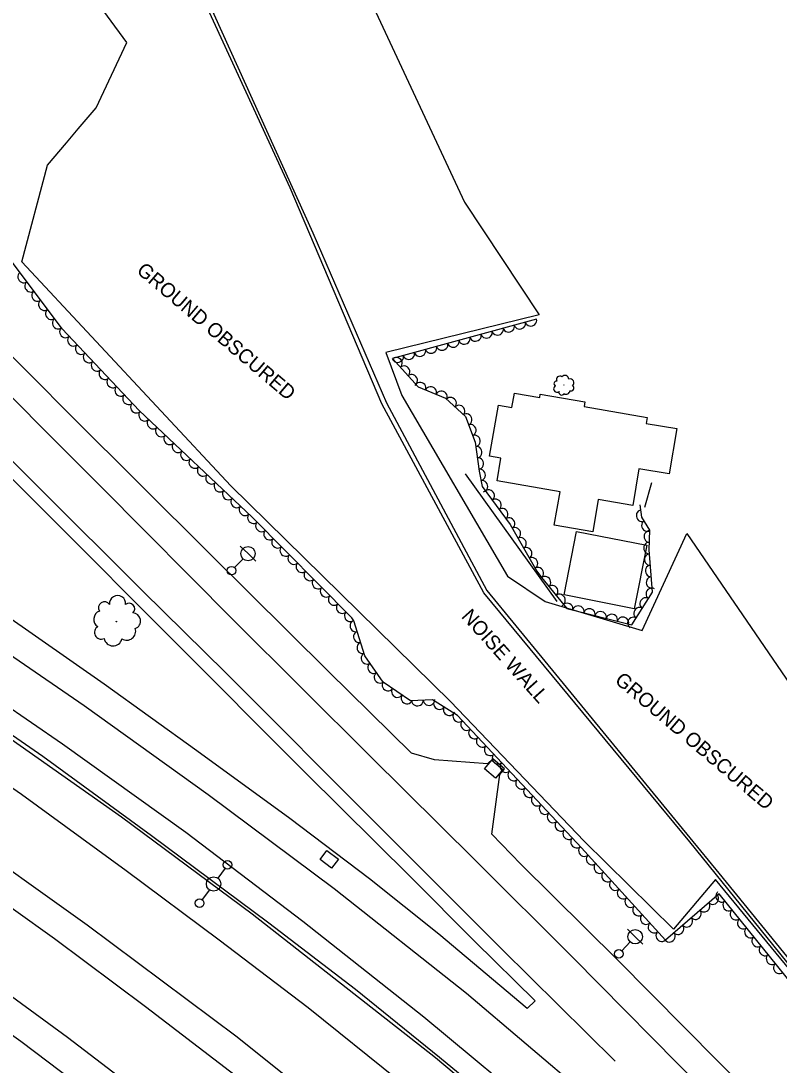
# Model space of a CAD drawing. Extents: x 1722896 to 1754269, y 648279 to 666297.
# Drawn here: x 1730871.3 to 1731135, y 652189.9 to 652553.4 of the extents above; entities that cross this region are included whole.
import ezdxf

# ---------------------------------------------------------------- set-up
doc = ezdxf.new("R2010")
doc.units = 0
for name, color, linetype in [('DESIGN - CENTERLINE - Proposed Text', 7, 'Continuous'), ('DESIGN - SCRATCH - User 1', 7, 'Continuous'), ('SURVEY - CENTERLINE - Preliminary', 7, 'Continuous'), ('SURVEY - CENTERLINE - Preliminary Text', 7, 'Continuous'), ('SURVEY - DRAINAGE - Natural Features', 7, 'Continuous'), ('SURVEY - DTM - Breaklines', 7, 'Continuous'), ('SURVEY - VEGETATION - Features with Text', 7, 'Continuous')]:
    doc.layers.add(name, color=color, linetype=linetype)

msp = doc.modelspace()

# ---------------------------------------------------------------- linework, layer by layer
at = {"layer": 'DESIGN - CENTERLINE - Proposed Text'}
for points in [[(1731067.21, 652419.17), (1731089.17, 652415.41), (1731088.82, 652413.32), (1731099.51, 652411.49), (1731096.81, 652395.73), (1731086.29, 652397.53), (1731084.1, 652384.76), (1731072.11, 652386.81), (1731070.19, 652375.59), (1731056.82, 652377.89), (1731058.82, 652389.53), (1731036.91, 652393.29), (1731038.28, 652401.25), (1731034.33, 652401.93), (1731037.37, 652419.64), (1731042.09, 652418.83), (1731042.95, 652423.81), (1731051.78, 652422.3), (1731051.97, 652423.43), (1731067.49, 652420.77)], [(1731084.61, 652348.81), (1731060.22, 652353.62), (1731064.59, 652375.72), (1731088.97, 652370.91)]]:
    msp.add_lwpolyline(points, close=True, dxfattribs=at)
msp.add_lwpolyline([(1731057.89, 652351.3), (1731025.92, 652395.8)], dxfattribs=at)
at = {"layer": 'DESIGN - SCRATCH - User 1'}
for points in [[(1731415.23, 651957.41), (1731346.29, 652048.74), (1731313.4, 652092.23), (1731280.89, 652137.12), (1731251.65, 652150.44), (1731164.59, 652192.63), (1731103.99, 652267.63), (1731032.33, 652354.35), (1730996.84, 652420.09), (1730964.93, 652495.33), (1730920.37, 652592.49), (1730898.63, 652642.39), (1730899.95, 652642.82), (1730933.45, 652566.86), (1730972.81, 652479.59), (1730998.47, 652420.42), (1731033.4, 652355.14), (1731114.02, 652256.72), (1731165.23, 652194.02), (1731248.69, 652153.02), (1731282.24, 652137.66), (1731349.81, 652046.37), (1731393.69, 651987.99), (1731416.02, 651958.14)], [(1731184.68, 652039.01), (1731109.02, 652111.22), (1731064.42, 652151.37), (1731015.53, 652192.51), (1730951.76, 652242.49), (1730906.24, 652276.23), (1730853.29, 652313.52), (1730791.6, 652354.66), (1730719.39, 652398.95), (1730662.55, 652431.47), (1730624.94, 652450.83)], [(1730625.93, 652451.9), (1730650.26, 652439.35), (1730686.31, 652419.66), (1730719.81, 652400.26), (1730755.55, 652378.55), (1730783.36, 652361.52), (1730813.17, 652342.25), (1730848.73, 652318.35), (1730878.93, 652297.5), (1730916.73, 652269.9), (1730957.6, 652239.46), (1730987.7, 652216.4), (1731016.88, 652192.76), (1731053.07, 652162.91), (1731079.29, 652139.47), (1731110.68, 652111.13), (1731142.33, 652081.33)]]:
    msp.add_lwpolyline(points, dxfattribs=at)
at = {"layer": 'SURVEY - CENTERLINE - Preliminary'}
for points in [[(1730972.83, 652603.53), (1731025.6, 652490.27), (1731051.53, 652451.13), (1730998.2, 652438.03), (1731003.79, 652422.96), (1731040.5, 652360.09), (1731053.68, 652351.3), (1731087.37, 652341.21), (1731102.96, 652374.95), (1731200.21, 652232.76)], [(1731162.67, 652194.07), (1731112.96, 652254.53), (1731098.31, 652237.27), (1731067.19, 652267.95), (1731020.7, 652316.47), (1730944.3, 652391.55), (1730871.61, 652469.51), (1730880.54, 652503.16), (1730887.17, 652510.98), (1730891.24, 652515.78), (1730897.5, 652523.15), (1730908.17, 652545.92), (1730893.45, 652566.1)]]:
    msp.add_lwpolyline(points, dxfattribs=at)
at = {"layer": 'SURVEY - CENTERLINE - Preliminary Text'}
for points in [[(1731169.96, 652134.42), (1731125.44, 652179.48), (1731078.79, 652226.64), (1731045.15, 652259.85), (1731035.13, 652270.28), (1731037.86, 652291.12), (1731039.55, 652293.11), (1731035.46, 652296.58), (1731033.59, 652294.84), (1731015.17, 652296.23), (1731007.12, 652298.48), (1730978.29, 652326.95), (1730936.8, 652368.15), (1730888.87, 652415.83), (1730846.66, 652458.3), (1730801.1, 652503.68), (1730763.06, 652542.15), (1730726.59, 652579.08), (1730704.92, 652600.69)], [(1730699.27, 652591.88), (1730734.05, 652556.32), (1730771.95, 652518.16), (1730809.27, 652481.29), (1730849.67, 652440.74), (1730899.23, 652391.25), (1730945.2, 652344.86), (1730992.78, 652297.53), (1731029.17, 652261.39), (1731063.45, 652227.26), (1731109.02, 652181.07), (1731162.34, 652127.31)], [(1731077.97, 652191.36), (1731038.58, 652230.31), (1730995.88, 652272.95), (1730942.44, 652326.59), (1730913.71, 652354.92), (1730877.51, 652391.02), (1730836.99, 652431.73), (1730798.41, 652470.26), (1730756.63, 652512.07), (1730718.21, 652550.58), (1730690.91, 652578.28)], [(1730688.22, 652575.09), (1730723.14, 652539.09), (1730750.47, 652511.56), (1730775.27, 652486.87), (1730810.39, 652451.84), (1730846.85, 652415.42), (1730882.81, 652379.45), (1730923.17, 652338.94), (1730970.33, 652291.71), (1731006.98, 652255.37), (1731029.16, 652233.02), (1731050.21, 652212.35), (1731047.39, 652209.64), (1731016.72, 652235.49), (1730992.56, 652254.77), (1730964.85, 652275.84), (1730932.52, 652299.32), (1730900.25, 652322.52), (1730865.55, 652346.81), (1730828.03, 652371.74), (1730792.13, 652394.5), (1730758.14, 652415.94), (1730719.7, 652438.2), (1730684.24, 652458.92)], [(1730637.46, 652472.36), (1730667.84, 652456.15), (1730704.13, 652435.53), (1730749.26, 652409.11), (1730802.86, 652375.86), (1730844.32, 652348.71), (1730893.33, 652315.16), (1730936.45, 652284.11), (1730980.22, 652251.45), (1731026.26, 652214.98), (1731067.84, 652179.69)], [(1731587.85, 651543.74), (1731554.53, 651591.86), (1731508.87, 651657.72), (1731461.56, 651723.65), (1731417.76, 651782.51), (1731384.14, 651826.41), (1731348.87, 651871.42), (1731308.12, 651919.53), (1731270.43, 651961.54), (1731234, 652000.43), (1731186, 652049.7), (1731143.95, 652090.19), (1731103.6, 652127.66), (1731054.73, 652170.64), (1731011.42, 652206.67), (1730969.33, 652239.94), (1730928.63, 652270.96), (1730885.78, 652301.63), (1730842.52, 652331.41), (1730780.08, 652372.14), (1730718.85, 652409.31), (1730662.64, 652441.18), (1730630.33, 652458.88)], [(1730618.34, 652439.02), (1730650.77, 652421.77), (1730691.08, 652399), (1730728.19, 652377.44), (1730763.09, 652355.85), (1730801.96, 652331.59), (1730839.18, 652306.53), (1730871.47, 652284.22), (1730907.95, 652257.65), (1730940.24, 652233.59), (1730971.18, 652210.01), (1731002.64, 652184.66), (1731032.21, 652160.17), (1731063.55, 652132.99), (1731097.54, 652102.18), (1731124.58, 652077.28), (1731156.41, 652046.95)], [(1731138.77, 652031.35), (1731108.47, 652060.26), (1731077.91, 652088.87), (1731042.79, 652120), (1730998.31, 652158.14), (1730946.56, 652199.69), (1730894.34, 652238.68), (1730847.55, 652272.08), (1730800.17, 652304.5), (1730758.55, 652331.13), (1730712.7, 652359.61), (1730667.84, 652385.38), (1730607.24, 652418.94)], [(1730602.25, 652409.81), (1730630.15, 652394.47), (1730660.99, 652377.38), (1730692.18, 652359.79), (1730718.79, 652343.79), (1730750.27, 652324.37), (1730785.98, 652301.43), (1730817.96, 652279.81), (1730854.32, 652254.45), (1730883.01, 652234), (1730914.64, 652210.29), (1730951.31, 652182.32), (1730987.15, 652153.5), (1731022.54, 652124.12), (1731052.75, 652097.57), (1731085.08, 652067.79), (1731118.03, 652036.86), (1731149.54, 652006.15)], [(1731592.81, 651391.29), (1731549.63, 651454.37), (1731491.17, 651538.79), (1731427.8, 651629.07), (1731385.16, 651689.48), (1731337.8, 651753.25), (1731295.32, 651806.88), (1731249.74, 651861.11), (1731202.94, 651914.16), (1731153.79, 651965.7), (1731107.83, 652011.26), (1731054.55, 652061.78), (1730996.82, 652113.2), (1730942.67, 652157.27), (1730887.56, 652199.54), (1730832.47, 652239.78), (1730770.05, 652283.03), (1730709.42, 652320.26), (1730647.01, 652356.15), (1730588.92, 652388.28)], [(1730583.92, 652378.76), (1730611.97, 652363.79), (1730650.69, 652342.33), (1730695.05, 652316.65), (1730740.68, 652289.25), (1730776.04, 652266.14), (1730818.78, 652235.8), (1730871.32, 652198.33), (1730917.39, 652163.36), (1730967.31, 652123.69), (1731005.29, 652091.49), (1731046.8, 652054.31), (1731077.58, 652025.84), (1731115.69, 651989.43), (1731148.06, 651956.9)]]:
    msp.add_lwpolyline(points, dxfattribs=at)
at = {"layer": 'SURVEY - DRAINAGE - Natural Features'}
for p, q in [((1731035.76, 652292.98), (1731035.76, 652292.98)), ((1730978.54, 652261.57), (1730978.54, 652261.57))]:
    msp.add_line(p, q, dxfattribs=at)
for points in [[(1731032.56, 652293.08), (1731035.15, 652296.12), (1731038.96, 652292.89), (1731036.37, 652289.84), (1731032.56, 652293.08)], [(1730975.34, 652261.47), (1730977.73, 652264.67), (1730981.74, 652261.67), (1730979.34, 652258.47), (1730975.34, 652261.47)]]:
    msp.add_lwpolyline(points, dxfattribs=at)
at = {"layer": 'SURVEY - DTM - Breaklines'}
for p, q in [((1730950.3, 652367.97), (1730947.61, 652370.58)), ((1730950.3, 652367.97), (1730952.99, 652365.35)), ((1730945.6, 652363.13), (1730948.56, 652366.18)), ((1730942.3, 652258.45), (1730939.8, 652255.01)), ((1730936.86, 652250.97), (1730934.36, 652247.54)), ((1731084.97, 652234.63), (1731082.26, 652237.22)), ((1731080.31, 652229.75), (1731083.25, 652232.82)), ((1731084.97, 652234.63), (1731087.68, 652232.04))]:
    msp.add_line(p, q, dxfattribs=at)
for centre, radius in [((1730950.3, 652367.97), 2.5), ((1730944.55, 652362.05), 1.5), ((1730943.19, 652259.66), 1.5), ((1730938.33, 652252.99), 2.5), ((1730933.47, 652246.32), 1.5), ((1731084.97, 652234.63), 2.5), ((1731079.28, 652228.66), 1.5)]:
    msp.add_circle(centre, radius, dxfattribs=at)
at = {"layer": 'SURVEY - VEGETATION - Features with Text'}
for points in [[(1731157.42, 652195.95), (1731114.13, 652249.62), (1731095.48, 652233.42), (1731066.26, 652265.59), (1731023.15, 652311.69), (1731014.5, 652317.12), (1731006.79, 652316.74), (1730997.26, 652323.24), (1730990.99, 652332.4), (1730987.09, 652344.57), (1730986.4, 652345.65), (1730951.78, 652380.69), (1730912.44, 652417.78), (1730885.63, 652446.22), (1730866.29, 652472.09), (1730836.36, 652497.88), (1730819.66, 652514.78), (1730798.55, 652537.6), (1730785.8, 652547.24), (1730752.38, 652583.97), (1730739.54, 652599.07), (1730722.36, 652610.22), (1730710.94, 652620.28)], [(1731050.64, 652449.62), (1731000.59, 652435.93), (1731009.43, 652426.03), (1731019, 652422.12), (1731025.91, 652415.69), (1731029.36, 652406.72), (1731030.69, 652396.7), (1731031.8, 652391.35), (1731041.44, 652378.14), (1731050.72, 652361.91), (1731052.37, 652359.65), (1731061.24, 652348.87), (1731083.84, 652343.23), (1731090.97, 652354.59), (1731089.81, 652369.35), (1731090.02, 652376.18), (1731087.32, 652380.72), (1731086.66, 652384.93)], [(1731088.27, 652384.11), (1731090.73, 652392.75)]]:
    msp.add_lwpolyline(points, dxfattribs=at)
for centre, radius in [((1731060.14, 652426.63), 0.0415), ((1730904.53, 652344.32), 0.0978)]:
    msp.add_circle(centre, radius, dxfattribs=at)
for centre, radius, start, end in [((1731058.77, 652428.57), 1.19, 52.8928, 209.6818), ((1731060.52, 652428.64), 1.36, 1.9456, 139.4698), ((1731057.8, 652425.33), 1.19, 115.0297, 308.4494), ((1731057.53, 652427.19), 0.817, 75.009, 253.7546), ((1731062.3, 652427.41), 1.35, 312.8414, 108.6799), ((1731062.69, 652425.58), 0.993, 243.0943, 58.0946), ((1731059.37, 652424.06), 0.904, 157.6483, 334.9675), ((1731060.96, 652424.7), 1.28, 232.9354, 359.7811), ((1730904.93, 652350.6), 2.8, 352.4829, 185.9026), ((1730900.4, 652349.09), 2.13, 35.1016, 212.4207), ((1730908.97, 652348.79), 1.92, 312.4622, 131.2079), ((1730899.66, 652345.12), 3.02, 110.3886, 237.2343), ((1730910.13, 652344.57), 2.8, 290.3461, 87.135), ((1730899.22, 652340.57), 2.34, 120.5476, 295.5478), ((1730908.05, 652341.02), 3.19, 239.3988, 16.9231), ((1730903.35, 652339.03), 3.17, 190.2947, 346.1331)]:
    msp.add_arc(centre, radius, start, end, dxfattribs=at)
for centre, major_axis in [((1730872.19, 652464.19), (-1.2, 1.6)), ((1730874.59, 652460.99), (-1.2, 1.6)), ((1730876.99, 652457.78), (-1.2, 1.6)), ((1730879.38, 652454.58), (-1.2, 1.6)), ((1730881.78, 652451.38), (-1.2, 1.6)), ((1730884.17, 652448.17), (-1.2, 1.6)), ((1731040.99, 652446.98), (-1.93, -0.53)), ((1731044.85, 652448.03), (-1.93, -0.53)), ((1731048.71, 652449.09), (-1.93, -0.53)), ((1730886.7, 652445.08), (-1.37, 1.46)), ((1730889.45, 652442.17), (-1.37, 1.46)), ((1731029.42, 652443.81), (-1.93, -0.53)), ((1731033.27, 652444.87), (-1.93, -0.53)), ((1731037.13, 652445.92), (-1.93, -0.53)), ((1730892.19, 652439.26), (-1.37, 1.46)), ((1731013.98, 652439.59), (-1.93, -0.53)), ((1731017.84, 652440.65), (-1.93, -0.53)), ((1731021.7, 652441.7), (-1.93, -0.53)), ((1731025.56, 652442.76), (-1.93, -0.53)), ((1730894.93, 652436.35), (-1.37, 1.46)), ((1731002.41, 652436.42), (-1.93, -0.53)), ((1731002, 652434.35), (1.33, -1.49)), ((1731006.27, 652437.48), (-1.93, -0.53)), ((1731010.13, 652438.53), (-1.93, -0.53)), ((1730897.68, 652433.44), (-1.37, 1.46)), ((1731004.66, 652431.36), (1.33, -1.49)), ((1730900.42, 652430.53), (-1.37, 1.46)), ((1730903.16, 652427.62), (-1.37, 1.46)), ((1731007.33, 652428.38), (1.33, -1.49)), ((1730905.91, 652424.71), (-1.37, 1.46)), ((1731010.21, 652425.71), (1.85, -0.76)), ((1731013.91, 652424.2), (1.85, -0.76)), ((1730908.65, 652421.8), (-1.37, 1.46)), ((1731017.62, 652422.69), (1.85, -0.76)), ((1731020.83, 652420.42), (1.46, -1.36)), ((1730911.39, 652418.88), (-1.37, 1.46)), ((1731023.76, 652417.69), (1.46, -1.36)), ((1730914.24, 652416.08), (-1.46, 1.37)), ((1730917.15, 652413.33), (-1.46, 1.37)), ((1731026.29, 652414.69), (0.72, -1.87)), ((1730920.06, 652410.59), (-1.46, 1.37)), ((1731027.73, 652410.96), (0.72, -1.87)), ((1730922.97, 652407.85), (-1.46, 1.37)), ((1731029.17, 652407.23), (0.72, -1.87)), ((1730925.88, 652405.1), (-1.46, 1.37)), ((1730928.79, 652402.36), (-1.46, 1.37)), ((1731029.82, 652403.29), (0.26, -1.98)), ((1730931.71, 652399.62), (-1.46, 1.37)), ((1731030.35, 652399.33), (0.26, -1.98)), ((1730934.62, 652396.87), (-1.46, 1.37)), ((1731030.97, 652395.38), (0.4, -1.96)), ((1730937.53, 652394.13), (-1.46, 1.37)), ((1730940.44, 652391.38), (-1.46, 1.37)), ((1731031.78, 652391.46), (0.4, -1.96)), ((1730943.35, 652388.64), (-1.46, 1.37)), ((1731034.09, 652388.21), (1.18, -1.62)), ((1730946.26, 652385.9), (-1.46, 1.37)), ((1731036.45, 652384.98), (1.18, -1.62)), ((1730949.17, 652383.15), (-1.46, 1.37)), ((1730952.07, 652380.4), (-1.41, 1.42)), ((1731038.8, 652381.75), (1.18, -1.62)), ((1731087.25, 652381.17), (-0.31, 1.98)), ((1730954.88, 652377.55), (-1.41, 1.42)), ((1731041.16, 652378.52), (1.18, -1.62)), ((1731089.13, 652377.67), (-1.02, 1.72)), ((1730957.69, 652374.71), (-1.41, 1.42)), ((1731043.19, 652375.07), (0.99, -1.74)), ((1731089.95, 652373.92), (0.06, 2)), ((1730960.5, 652371.86), (-1.41, 1.42)), ((1731045.18, 652371.6), (0.99, -1.74)), ((1731089.83, 652369.92), (0.06, 2)), ((1730963.32, 652369.02), (-1.41, 1.42)), ((1730966.13, 652366.17), (-1.41, 1.42)), ((1731047.16, 652368.13), (0.99, -1.74)), ((1731090.08, 652365.93), (-0.16, 1.99)), ((1730968.94, 652363.33), (-1.41, 1.42)), ((1731049.15, 652364.66), (0.99, -1.74)), ((1731051.21, 652361.23), (1.18, -1.62)), ((1731090.39, 652361.94), (-0.16, 1.99)), ((1730971.75, 652360.48), (-1.41, 1.42)), ((1731053.66, 652358.08), (1.27, -1.54)), ((1731090.7, 652357.95), (-0.16, 1.99)), ((1730974.56, 652357.64), (-1.41, 1.42)), ((1730977.37, 652354.79), (-1.41, 1.42)), ((1731056.2, 652354.99), (1.27, -1.54)), ((1731090.64, 652354.06), (1.06, 1.69)), ((1730980.18, 652351.94), (-1.41, 1.42)), ((1731058.75, 652351.9), (1.27, -1.54)), ((1731088.51, 652350.67), (1.06, 1.69)), ((1730982.99, 652349.1), (-1.41, 1.42)), ((1731061.32, 652348.85), (1.94, -0.48)), ((1731065.2, 652347.89), (1.94, -0.48)), ((1731069.08, 652346.92), (1.94, -0.48)), ((1731086.38, 652347.28), (1.06, 1.69)), ((1730985.8, 652346.25), (-1.41, 1.42)), ((1731072.96, 652345.95), (1.94, -0.48)), ((1731076.84, 652344.98), (1.94, -0.48)), ((1731080.72, 652344.01), (1.94, -0.48)), ((1731084.26, 652343.89), (1.06, 1.69)), ((1730987.66, 652342.79), (-0.61, 1.9)), ((1730988.88, 652338.98), (-0.61, 1.9)), ((1730990.1, 652335.17), (-0.61, 1.9)), ((1730991.61, 652331.5), (-1.13, 1.65)), ((1730993.87, 652328.2), (-1.13, 1.65)), ((1730996.13, 652324.9), (-1.13, 1.65)), ((1730998.9, 652322.12), (-1.65, 1.13)), ((1731002.21, 652319.86), (-1.65, 1.13)), ((1731005.51, 652317.61), (-1.65, 1.13)), ((1731009.24, 652316.86), (-2, -0.1)), ((1731013.24, 652317.05), (-2, -0.1)), ((1731016.82, 652315.66), (-1.69, 1.06)), ((1731020.21, 652313.54), (-1.69, 1.06)), ((1731023.51, 652311.31), (-1.37, 1.46)), ((1731026.24, 652308.39), (-1.37, 1.46)), ((1731028.97, 652305.47), (-1.37, 1.46)), ((1731031.7, 652302.55), (-1.37, 1.46)), ((1731034.44, 652299.62), (-1.37, 1.46)), ((1731037.17, 652296.7), (-1.37, 1.46)), ((1731039.9, 652293.78), (-1.37, 1.46)), ((1731042.63, 652290.86), (-1.37, 1.46)), ((1731045.36, 652287.94), (-1.37, 1.46)), ((1731048.1, 652285.02), (-1.37, 1.46)), ((1731050.83, 652282.09), (-1.37, 1.46)), ((1731053.56, 652279.17), (-1.37, 1.46)), ((1731056.29, 652276.25), (-1.37, 1.46)), ((1731059.02, 652273.33), (-1.37, 1.46)), ((1731061.76, 652270.41), (-1.37, 1.46)), ((1731064.49, 652267.49), (-1.37, 1.46)), ((1731067.21, 652264.55), (-1.34, 1.48)), ((1731069.89, 652261.59), (-1.34, 1.48)), ((1731072.58, 652258.63), (-1.34, 1.48)), ((1731075.27, 652255.67), (-1.34, 1.48)), ((1731077.96, 652252.71), (-1.34, 1.48)), ((1731080.65, 652249.75), (-1.34, 1.48)), ((1731083.34, 652246.78), (-1.34, 1.48)), ((1731112.05, 652247.81), (-1.51, -1.31)), ((1731114.91, 652248.65), (-1.26, 1.56)), ((1731117.42, 652245.54), (-1.26, 1.56)), ((1731086.03, 652243.82), (-1.34, 1.48)), ((1731106.01, 652242.57), (-1.51, -1.31)), ((1731109.03, 652245.19), (-1.51, -1.31)), ((1731119.94, 652242.43), (-1.26, 1.56)), ((1731088.72, 652240.86), (-1.34, 1.48)), ((1731102.99, 652239.94), (-1.51, -1.31)), ((1731122.45, 652239.31), (-1.26, 1.56)), ((1731091.41, 652237.9), (-1.34, 1.48)), ((1731094.1, 652234.94), (-1.34, 1.48)), ((1731099.97, 652237.32), (-1.51, -1.31)), ((1731124.96, 652236.2), (-1.26, 1.56)), ((1731096.95, 652234.7), (-1.51, -1.31)), ((1731127.47, 652233.09), (-1.26, 1.56)), ((1731129.98, 652229.97), (-1.26, 1.56)), ((1731132.49, 652226.86), (-1.26, 1.56)), ((1731135, 652223.75), (-1.26, 1.56))]:
    msp.add_ellipse(centre, major_axis=major_axis, ratio=0.940188, start_param=0, end_param=3.141593, dxfattribs=at)

# ---------------------------------------------------------------- texts
at = {"layer": 'DESIGN - SCRATCH - User 1'}
msp.add_text('NOISE WALL', height=5, rotation=311.7916, dxfattribs=at).set_placement((1731024.27, 652345.96))
at = {"layer": 'SURVEY - CENTERLINE - Preliminary'}
for rotation, p in [(319.6804, (1730911.22, 652465.97)), (319.6769, (1731077.54, 652323.35))]:
    msp.add_text('GROUND OBSCURED', height=5, rotation=rotation, dxfattribs=at).set_placement(p)

doc.saveas('drawing.dxf')
